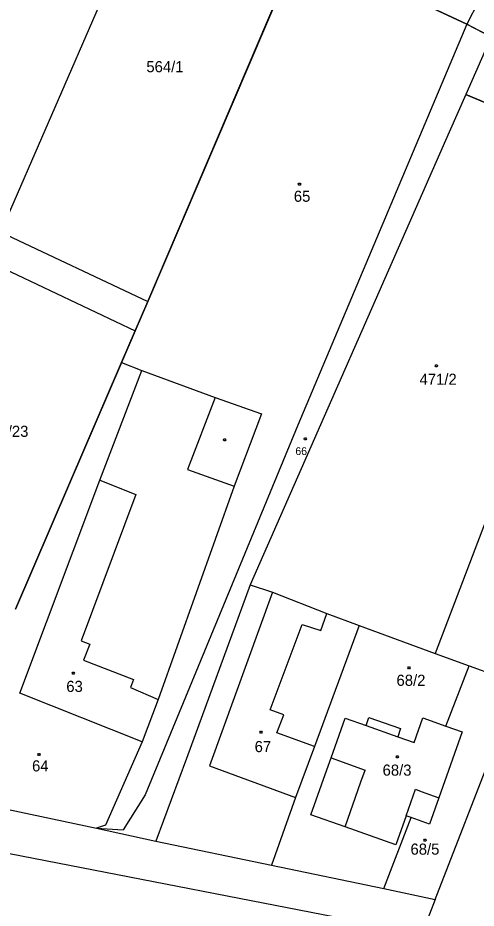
# Model space of a CAD drawing. Extents: x -634640 to -629202, y -1196156 to -1190068.
# Drawn here: x -631260.2 to -631190.1, y -1192622.8 to -1192486.6 of the extents above; entities that cross this region are included whole.
import ezdxf

# ---------------------------------------------------------------- set-up
doc = ezdxf.new("R2010")
doc.units = 0
for name, color, linetype in [('Obvod převzatý', 7, 'Continuous'), ('Obvod šetřený', 7, 'Continuous'), ('Vrstva 1', 7, 'Continuous'), ('Vrstva 2', 7, 'Continuous'), ('Vrstva 3', 7, 'Continuous'), ('Vrstva 4', 7, 'Continuous'), ('Vrstva 5', 7, 'Continuous')]:
    doc.layers.add(name, color=color, linetype=linetype)

msp = doc.modelspace()

# ---------------------------------------------------------------- linework, layer by layer
at = {"layer": 'Obvod převzatý'}
for points in [[(-631217.09, -1192475.48), (-631240.35, -1192529.94), (-631242.28, -1192534.46), (-631252.45, -1192558.15), (-631260.56, -1192577.01)], [(-631187.8, -1192489.45), (-631189.665, -1192488.5), (-631191.53, -1192487.55), (-631204.31, -1192481.515), (-631217.09, -1192475.48)]]:
    msp.add_lwpolyline(points, dxfattribs=at)
at = {"layer": 'Obvod šetřený'}
msp.add_lwpolyline([(-631187.8, -1192489.45), (-631191.68, -1192498.28), (-631179.695, -1192503.34)], dxfattribs=at)
at = {"layer": 'Vrstva 1'}
for p, q in [((-631262.82, -1192519.37), (-631240.16, -1192467.12)), ((-631240.35, -1192529.94), (-631217.09, -1192475.48)), ((-631217.09, -1192475.48), (-631191.53, -1192487.55)), ((-631189.75, -1192484.04), (-631191.53, -1192487.55)), ((-631191.53, -1192487.55), (-631217.35, -1192548.86)), ((-631191.53, -1192487.55), (-631187.8, -1192489.45)), ((-631187.8, -1192489.45), (-631191.68, -1192498.28)), ((-631191.68, -1192498.28), (-631194.22, -1192504.05)), ((-631167.71, -1192508.4), (-631191.68, -1192498.28)), ((-631194.22, -1192504.05), (-631224.67, -1192573.31)), ((-631167.71, -1192508.4), (-631196.34, -1192583.78)), ((-631262.82, -1192519.37), (-631240.35, -1192529.94)), ((-631263.5, -1192524.4), (-631242.28, -1192534.46)), ((-631242.28, -1192534.46), (-631240.35, -1192529.94)), ((-631244.34, -1192539.29), (-631242.28, -1192534.46)), ((-631260.56, -1192577.01), (-631244.34, -1192539.29)), ((-631244.34, -1192539.29), (-631241.26, -1192540.49)), ((-631247.69, -1192557.27), (-631241.26, -1192540.49)), ((-631241.26, -1192540.49), (-631230.03, -1192544.62)), ((-631230.03, -1192544.62), (-631222.92, -1192547.15)), ((-631222.92, -1192547.15), (-631227.13, -1192558.19)), ((-631217.35, -1192548.86), (-631240.74, -1192605.41)), ((-631259.89, -1192589.89), (-631247.69, -1192557.27)), ((-631227.13, -1192558.19), (-631238.75, -1192590.83)), ((-631224.67, -1192573.31), (-631234.43, -1192599.85)), ((-631224.67, -1192573.31), (-631221.23, -1192574.41)), ((-631221.23, -1192574.41), (-631212.95, -1192577.7)), ((-631212.95, -1192577.7), (-631207.99, -1192579.51)), ((-631207.99, -1192579.51), (-631214.83, -1192598.03)), ((-631207.99, -1192579.51), (-631196.34, -1192583.78)), ((-631196.34, -1192583.78), (-631191.18, -1192585.67)), ((-631194.71, -1192594.91), (-631191.18, -1192585.67)), ((-631191.18, -1192585.67), (-631183.57, -1192588.45)), ((-631196.36, -1192621.41), (-631183.57, -1192588.45)), ((-631241.2, -1192597.32), (-631259.89, -1192589.89)), ((-631238.75, -1192590.83), (-631241.2, -1192597.32)), ((-631212.27, -1192599.76), (-631210.11, -1192593.68)), ((-631210.11, -1192593.68), (-631206.94, -1192594.81)), ((-631206.94, -1192594.81), (-631206.49, -1192593.57)), ((-631206.49, -1192593.57), (-631201.64, -1192595.29)), ((-631199.59, -1192597.42), (-631198.24, -1192593.66)), ((-631198.24, -1192593.66), (-631194.71, -1192594.91)), ((-631194.71, -1192594.91), (-631192.22, -1192595.8)), ((-631198.41, -1192626.69), (-631355.77, -1192596.21)), ((-631201.64, -1192595.29), (-631202.08, -1192596.54)), ((-631202.08, -1192596.54), (-631199.59, -1192597.42)), ((-631192.22, -1192595.8), (-631195.81, -1192605.9)), ((-631241.2, -1192597.32), (-631246.78, -1192610.05)), ((-631214.83, -1192598.03), (-631217.72, -1192605.81)), ((-631234.43, -1192599.85), (-631239.08, -1192612.49)), ((-631212.93, -1192601.6), (-631212.27, -1192599.76)), ((-631215.37, -1192608.47), (-631212.93, -1192601.6)), ((-631272.85, -1192605.26), (-631248.17, -1192610.53)), ((-631240.74, -1192605.41), (-631244.11, -1192610.77)), ((-631217.72, -1192605.81), (-631221.41, -1192616.18)), ((-631195.81, -1192605.9), (-631197.24, -1192609.93)), ((-631210.14, -1192610.3), (-631215.37, -1192608.47)), ((-631204.19, -1192619.77), (-631200.04, -1192608.9)), ((-631200.81, -1192608.62), (-631202.4, -1192613.07)), ((-631200.04, -1192608.9), (-631200.81, -1192608.62)), ((-631197.24, -1192609.93), (-631200.04, -1192608.9)), ((-631246.78, -1192610.05), (-631248.17, -1192610.53)), ((-631248.17, -1192610.53), (-631239.08, -1192612.49)), ((-631248.17, -1192610.53), (-631244.11, -1192610.77)), ((-631202.4, -1192613.07), (-631210.14, -1192610.3)), ((-631239.08, -1192612.49), (-631221.41, -1192616.18)), ((-631221.41, -1192616.18), (-631204.19, -1192619.77)), ((-631204.19, -1192619.77), (-631196.36, -1192621.41)), ((-631196.36, -1192621.41), (-631198.41, -1192626.69))]:
    msp.add_line(p, q, dxfattribs=at)
at = {"layer": 'Vrstva 3'}
for points in [[(-631217.03, -1192511.86), (-631216.94, -1192512.01), (-631217.03, -1192512.16), (-631217.21, -1192512.16), (-631217.3, -1192512.01), (-631217.21, -1192511.86), (-631217.03, -1192511.86)], [(-631196.07, -1192539.65), (-631195.98, -1192539.8), (-631196.07, -1192539.95), (-631196.25, -1192539.95), (-631196.34, -1192539.8), (-631196.25, -1192539.65), (-631196.07, -1192539.65)], [(-631216.16, -1192550.8), (-631216.07, -1192550.95), (-631216.16, -1192551.1), (-631216.34, -1192551.1), (-631216.43, -1192550.95), (-631216.34, -1192550.8), (-631216.16, -1192550.8)], [(-631200.28, -1192585.84), (-631200.19, -1192585.99), (-631200.28, -1192586.14), (-631200.46, -1192586.14), (-631200.55, -1192585.99), (-631200.46, -1192585.84), (-631200.28, -1192585.84)], [(-631256.88, -1192599.1), (-631256.79, -1192599.25), (-631256.88, -1192599.4), (-631257.06, -1192599.4), (-631257.15, -1192599.25), (-631257.06, -1192599.1), (-631256.88, -1192599.1)], [(-631197.81, -1192612.23), (-631197.72, -1192612.38), (-631197.81, -1192612.53), (-631197.99, -1192612.53), (-631198.08, -1192612.38), (-631197.99, -1192612.23), (-631197.81, -1192612.23)]]:
    msp.add_lwpolyline(points, dxfattribs=at)
at = {"layer": 'Vrstva 4'}
for p, q in [((-631230.03, -1192544.62), (-631234.26, -1192555.67)), ((-631234.26, -1192555.67), (-631227.13, -1192558.19)), ((-631247.69, -1192557.27), (-631242.15, -1192559.46)), ((-631242.15, -1192559.46), (-631250.53, -1192581.86)), ((-631221.23, -1192574.41), (-631230.89, -1192601.01)), ((-631213.84, -1192580.3), (-631212.95, -1192577.7)), ((-631221.63, -1192592.43), (-631216.73, -1192579.34)), ((-631216.73, -1192579.34), (-631213.84, -1192580.3)), ((-631250.53, -1192581.86), (-631249.22, -1192582.38)), ((-631249.22, -1192582.38), (-631250.15, -1192584.83)), ((-631250.15, -1192584.83), (-631242.5, -1192587.77)), ((-631242.5, -1192587.77), (-631242.96, -1192589)), ((-631242.96, -1192589), (-631238.75, -1192590.83)), ((-631219.54, -1192593.16), (-631221.63, -1192592.43)), ((-631220.57, -1192595.94), (-631219.54, -1192593.16)), ((-631206.94, -1192594.81), (-631202.08, -1192596.54)), ((-631214.83, -1192598.03), (-631220.57, -1192595.94)), ((-631212.27, -1192599.76), (-631207.07, -1192601.66)), ((-631230.89, -1192601.01), (-631217.72, -1192605.81)), ((-631207.72, -1192603.45), (-631207.07, -1192601.66)), ((-631210.14, -1192610.3), (-631207.72, -1192603.45)), ((-631200.81, -1192608.62), (-631199.36, -1192604.58)), ((-631199.36, -1192604.58), (-631198.51, -1192604.9)), ((-631198.51, -1192604.9), (-631195.81, -1192605.9))]:
    msp.add_line(p, q, dxfattribs=at)
at = {"layer": 'Vrstva 5'}
for points in [[(-631228.5, -1192550.98), (-631228.41, -1192551.13), (-631228.5, -1192551.28), (-631228.68, -1192551.28), (-631228.77, -1192551.13), (-631228.68, -1192550.98), (-631228.5, -1192550.98)], [(-631251.63, -1192586.66), (-631251.54, -1192586.81), (-631251.63, -1192586.96), (-631251.81, -1192586.96), (-631251.9, -1192586.81), (-631251.81, -1192586.66), (-631251.63, -1192586.66)], [(-631222.91, -1192595.69), (-631222.82, -1192595.84), (-631222.91, -1192595.99), (-631223.09, -1192595.99), (-631223.18, -1192595.84), (-631223.09, -1192595.69), (-631222.91, -1192595.69)], [(-631202.07, -1192599.47), (-631201.98, -1192599.62), (-631202.07, -1192599.77), (-631202.25, -1192599.77), (-631202.34, -1192599.62), (-631202.25, -1192599.47), (-631202.07, -1192599.47)]]:
    msp.add_lwpolyline(points, dxfattribs=at)

# ---------------------------------------------------------------- texts
at = {"layer": 'Vrstva 2'}
for s, height, p in [('564/1', 1.7, (-631240.553, -1192494.88)), ('65', 1.7, (-631217.983, -1192514.7)), ('471/2', 1.7, (-631198.753, -1192542.7)), ('564/23', 1.7, (-631265.553, -1192550.66)), ('66', 1.19, (-631217.74, -1192553.44)), ('68/2', 1.7, (-631202.273, -1192588.75)), ('63', 1.7, (-631252.803, -1192589.68)), ('67', 1.7, (-631223.983, -1192598.89)), ('64', 1.7, (-631258.043, -1192601.84)), ('68/3', 1.7, (-631204.403, -1192602.49)), ('68/5', 1.7, (-631200.133, -1192614.58))]:
    msp.add_text(s, height=height, dxfattribs=at).set_placement(p)

doc.saveas('drawing.dxf')
